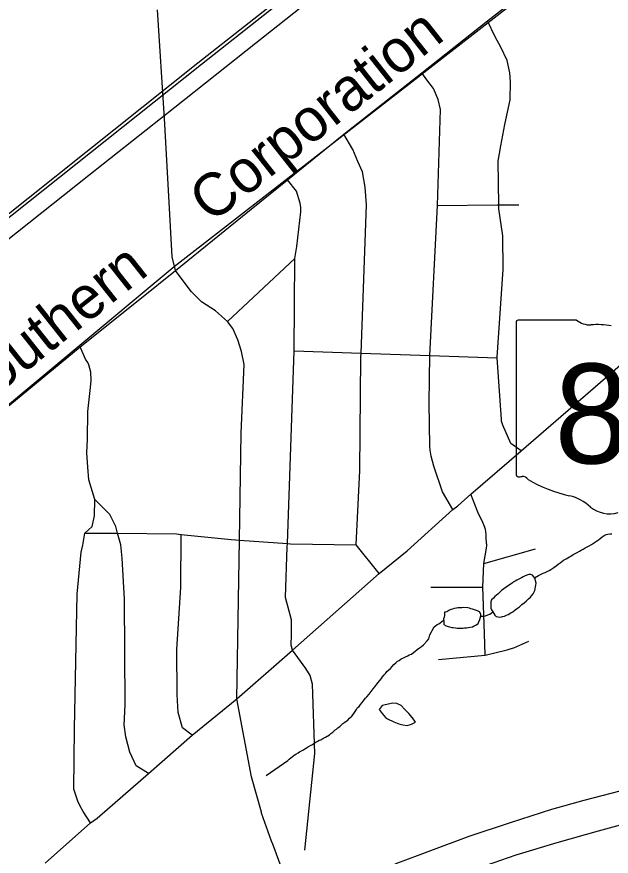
# Model space of a CAD drawing. Extents: x 0 to 34, y 0 to 22.
# Drawn here: x 7.421 to 8.206, y 14.779 to 15.889 of the extents above; entities that cross this region are included whole.
import ezdxf

# ---------------------------------------------------------------- set-up
doc = ezdxf.new("R2010")
doc.units = 0
for name, color, linetype in [('GM_X_City_Street', 7, 'Continuous'), ('GM_X_Interstate_Route', 7, 'Continuous'), ('GM_X_Minor_Lake', 7, 'Continuous'), ('GM_X_Minor_River', 7, 'Continuous'), ('GM_X_Rail_Line', 7, 'Continuous'), ('GM_X_Rail_Line_Text', 7, 'Continuous'), ('GM_X_State_Location', 7, 'Continuous'), ('GM_X_State_Route', 7, 'Continuous'), ('GM_X_State_Shield', 7, 'Continuous'), ('GM_X_US_Route', 7, 'Continuous')]:
    doc.layers.add(name, color=color, linetype=linetype)

msp = doc.modelspace()

# ---------------------------------------------------------------- linework, layer by layer
at = {"layer": 'GM_X_City_Street'}
for p, q in [((8.0578, 15.6405), (8.0841, 15.6407)), ((7.699, 15.4863), (7.7879, 15.5698)), ((8.0379, 15.1664), (8.1062, 15.1859)), ((7.9677, 15.1353), (8.0364, 15.1349))]:
    msp.add_line(p, q, dxfattribs=at)
for points in [[(8.0874, 15.3152), (8.0737, 15.3249), (8.0628, 15.3493), (8.062, 15.3519), (8.0613, 15.3547), (8.061, 15.3569), (8.0556, 15.4382), (8.0555, 15.4393), (8.0635, 15.555), (8.0631, 15.5995), (8.0579, 15.6352), (8.0578, 15.6405), (8.0566, 15.6985), (8.0602, 15.7187), (8.0655, 15.747), (8.0726, 15.7796), (8.0731, 15.8032), (8.0724, 15.815), (8.0685, 15.8312), (8.0604, 15.8489), (8.0528, 15.8628), (8.0427, 15.884)], [(7.997, 15.2378), (7.9834, 15.2612), (7.9718, 15.2951), (7.9682, 15.3085), (7.9669, 15.3164), (7.9665, 15.3216), (7.9657, 15.3787), (7.9665, 15.4413), (7.9766, 15.6397), (7.9808, 15.7668), (7.9776, 15.7798), (7.9715, 15.7944), (7.9624, 15.8057), (7.9559, 15.8151)], [(7.8996, 15.153), (7.8693, 15.1912), (7.8738, 15.2894), (7.8754, 15.4388), (7.8756, 15.4444), (7.8828, 15.6408), (7.881, 15.664), (7.8773, 15.6843), (7.8715, 15.6979), (7.8647, 15.7138), (7.8527, 15.7338)], [(7.8012, 14.7872), (7.8146, 14.915), (7.8115, 15.0068), (7.8085, 15.0185), (7.8028, 15.0276), (7.7849, 15.0518), (7.7831, 15.0586), (7.7838, 15.0725), (7.7838, 15.0918), (7.7756, 15.1214), (7.7781, 15.1885), (7.7782, 15.1929), (7.7874, 15.4474), (7.7879, 15.5698), (7.7909, 15.5857), (7.7962, 15.6315), (7.796, 15.6334), (7.796, 15.6369), (7.795, 15.6429), (7.7903, 15.6586), (7.7783, 15.6736)], [(7.9766, 15.6397), (8.0553, 15.6405), (8.0578, 15.6405)], [(7.5946, 14.8886), (7.5784, 14.8987), (7.57, 14.9169), (7.5649, 14.9374), (7.5625, 14.9529), (7.5638, 14.9791), (7.5629, 15.1193), (7.5599, 15.1736), (7.5579, 15.1911), (7.5538, 15.2063), (7.5514, 15.2155), (7.5436, 15.2312), (7.5236, 15.2512), (7.516, 15.2772), (7.5143, 15.2938), (7.5131, 15.3127), (7.514, 15.3306), (7.5145, 15.3674), (7.5181, 15.399), (7.5189, 15.4084), (7.5183, 15.4195), (7.516, 15.429), (7.5143, 15.432), (7.5112, 15.4365), (7.5045, 15.4529)], [(7.7874, 15.4474), (7.8756, 15.4444), (7.9665, 15.4413), (8.0556, 15.4382)], [(7.5178, 14.8233), (7.5083, 14.8385), (7.5043, 14.8457), (7.5014, 14.8521), (7.4962, 14.868), (7.4968, 14.9476), (7.5006, 15.1257), (7.5055, 15.1812), (7.5077, 15.1907), (7.5107, 15.2067), (7.5201, 15.2155), (7.5234, 15.2296), (7.5236, 15.2512)], [(8.0396, 15.0453), (8.0387, 15.0738), (8.0364, 15.1349), (8.0379, 15.1664), (8.0414, 15.1865), (8.0417, 15.1903), (8.0411, 15.1996), (8.0408, 15.2041), (8.0403, 15.2086), (8.04, 15.2113), (8.0387, 15.2154), (8.0367, 15.2206), (8.0298, 15.2342), (8.0208, 15.2579)], [(7.5107, 15.2067), (7.5538, 15.2063), (7.6315, 15.2055), (7.6378, 15.2049), (7.7041, 15.1983), (7.7099, 15.1978), (7.7148, 15.1974), (7.7782, 15.1929), (7.7825, 15.1926), (7.8693, 15.1912)], [(7.6523, 14.9395), (7.6397, 14.9492), (7.6338, 14.9693), (7.6325, 14.9933), (7.6321, 15.0529), (7.6373, 15.1346), (7.6378, 15.2049)], [(7.9781, 15.0394), (8.0396, 15.0453), (8.0686, 15.0521), (8.0728, 15.0534), (8.0773, 15.0549), (8.0972, 15.0639)]]:
    msp.add_lwpolyline(points, dxfattribs=at)
at = {"layer": 'GM_X_Interstate_Route'}
for points in [[(7.9205, 14.7695), (7.9678, 14.7868), (8.0184, 14.8059), (8.073, 14.8241), (8.1279, 14.8414), (8.1706, 14.8535), (8.2301, 14.869), (8.281, 14.8809), (8.383, 14.9014), (8.6062, 14.9451), (8.8651, 14.996), (8.9001, 15.0028)], [(7.873, 14.7025), (7.9366, 14.729), (8.0198, 14.7601), (8.0806, 14.781), (8.1348, 14.7973), (8.1895, 14.813), (8.2377, 14.8261), (8.2893, 14.8384), (8.3875, 14.8584), (8.6106, 14.9021), (8.8639, 14.9516), (8.9001, 14.9587)]]:
    msp.add_lwpolyline(points, dxfattribs=at)
at = {"layer": 'GM_X_Minor_Lake'}
for points in [[(8.0476, 15.1061), (8.0512, 15.1001), (8.0523, 15.0982), (8.0543, 15.0964), (8.0566, 15.0957), (8.0597, 15.0954), (8.0627, 15.0962), (8.065, 15.0966), (8.068, 15.0979), (8.0702, 15.0991), (8.0736, 15.101), (8.0762, 15.1026), (8.0792, 15.105), (8.0822, 15.1074), (8.0848, 15.1093), (8.0882, 15.1121), (8.0912, 15.1144), (8.0942, 15.1172), (8.0968, 15.1195), (8.0997, 15.1219), (8.1008, 15.1238), (8.1031, 15.1262), (8.1045, 15.1289), (8.1052, 15.1308), (8.1059, 15.1327), (8.1063, 15.1354), (8.1066, 15.1377), (8.1069, 15.1404), (8.1052, 15.1468), (8.104, 15.1487), (8.1024, 15.1509), (8.1001, 15.152), (8.0974, 15.1519), (8.0948, 15.1511), (8.0918, 15.1495), (8.0899, 15.1487), (8.0877, 15.1475), (8.085, 15.1463), (8.0831, 15.1451), (8.0813, 15.1443), (8.0794, 15.1431), (8.0768, 15.1415), (8.0757, 15.141)], [(8.0757, 15.141), (8.0674, 15.1352), (8.0644, 15.1328), (8.0614, 15.1308), (8.0592, 15.1285), (8.0566, 15.1265), (8.0547, 15.1246), (8.0525, 15.1226), (8.0506, 15.1206), (8.048, 15.1183), (8.0473, 15.1156), (8.047, 15.1126), (8.0471, 15.1107), (8.0472, 15.1068), (8.0476, 15.1061)], [(7.986, 15.1019), (7.986, 15.1), (7.9857, 15.0977), (7.9854, 15.0954), (7.9847, 15.0931), (7.9848, 15.0896), (7.9852, 15.0858), (7.9883, 15.084), (7.9906, 15.0829), (7.9926, 15.0826), (7.9956, 15.0819), (7.9975, 15.0816), (8.0002, 15.0813), (8.0025, 15.081), (8.0059, 15.081), (8.0086, 15.0807), (8.0105, 15.0808), (8.0124, 15.0812), (8.0151, 15.0813), (8.0173, 15.0817), (8.0227, 15.0826), (8.0249, 15.0838), (8.0275, 15.085), (8.0302, 15.087), (8.0312, 15.0893), (8.0327, 15.0924), (8.0337, 15.097), (8.0337, 15.0993), (8.0321, 15.1023), (8.0297, 15.1037), (8.027, 15.1048), (8.0228, 15.1062), (8.0209, 15.1066), (8.019, 15.1073), (8.0167, 15.1076), (8.0167, 15.1076)], [(8.0167, 15.1076), (8.011, 15.1082), (8.0087, 15.1078), (8.006, 15.1077), (8.0037, 15.1076), (8.0018, 15.1072), (7.9988, 15.1068), (7.9965, 15.1059), (7.9943, 15.1055), (7.9916, 15.1043), (7.989, 15.1027), (7.9864, 15.1019), (7.9864, 15.1019), (7.986, 15.1019)], [(7.9036, 14.9787), (7.8995, 14.9733), (7.9033, 14.968), (7.9079, 14.9628), (7.9106, 14.9611)], [(7.9475, 14.9567), (7.9436, 14.9624), (7.9386, 14.968), (7.9333, 14.9733), (7.9287, 14.9785), (7.9229, 14.9815), (7.9176, 14.9819), (7.9036, 14.9787)], [(7.9106, 14.9611), (7.919, 14.9572), (7.9255, 14.9546), (7.9308, 14.9531), (7.9365, 14.9524), (7.9422, 14.954), (7.9475, 14.9567)]]:
    msp.add_lwpolyline(points, dxfattribs=at)
at = {"layer": 'GM_X_Minor_River'}
for points in [[(8.1047, 15.1476), (8.1101, 15.1507), (8.1119, 15.1515), (8.1138, 15.1523), (8.1161, 15.1535), (8.1191, 15.1547), (8.1217, 15.156), (8.124, 15.1572), (8.1266, 15.1584), (8.1304, 15.1611), (8.1333, 15.1635), (8.136, 15.1655), (8.1386, 15.1674), (8.1408, 15.169), (8.1431, 15.1706), (8.1449, 15.1718), (8.1468, 15.1726), (8.1487, 15.1738), (8.151, 15.175), (8.1528, 15.1762), (8.1558, 15.1782), (8.1577, 15.179), (8.1611, 15.1809), (8.1645, 15.1829), (8.1663, 15.1841), (8.169, 15.1853), (8.172, 15.1869), (8.1746, 15.1885), (8.1772, 15.1897), (8.1802, 15.1917), (8.1829, 15.1933), (8.1866, 15.1961), (8.1892, 15.1977), (8.1915, 15.1996), (8.1941, 15.2016), (8.1971, 15.2036), (8.1997, 15.2048), (8.2016, 15.2052), (8.2043, 15.2057), (8.2069, 15.2057)], [(8.0337, 15.0969), (8.0372, 15.0967), (8.0402, 15.0971), (8.0432, 15.0984), (8.0458, 15.0996), (8.0477, 15.1008), (8.0498, 15.1024)], [(7.7501, 14.8862), (7.7788, 14.9058), (7.7807, 14.9078), (7.7829, 14.9094), (7.7848, 14.9113), (7.787, 14.9129), (7.7893, 14.9145), (7.7923, 14.9161), (7.7941, 14.9173), (7.796, 14.9184), (7.7986, 14.9197), (7.8013, 14.9212), (7.8035, 14.9228), (7.8061, 14.9244), (7.8088, 14.9256), (7.8107, 14.9268), (7.8133, 14.9284), (7.8159, 14.93), (7.8185, 14.9316), (7.8204, 14.9328), (7.8223, 14.9332), (7.8249, 14.9348), (7.8287, 14.9368), (7.8339, 14.94), (7.8358, 14.9415), (7.8384, 14.9435), (7.8414, 14.9463), (7.8433, 14.9474), (7.8451, 14.949), (7.8481, 14.9514), (7.8515, 14.9549), (7.8541, 14.9565), (7.8559, 14.958), (7.8582, 14.9592), (7.8604, 14.962), (7.8634, 14.9647), (7.8652, 14.9667), (7.8671, 14.9694), (7.8697, 14.9732), (7.8711, 14.9759), (7.873, 14.9775), (7.8748, 14.9798), (7.877, 14.9826), (7.8796, 14.9861), (7.8815, 14.9884), (7.8833, 14.9903), (7.8863, 14.9935), (7.8889, 14.997), (7.8918, 15.0005), (7.894, 15.0032), (7.8966, 15.0067), (7.8999, 15.0113), (7.9025, 15.0144), (7.904, 15.0164), (7.9062, 15.0191), (7.9077, 15.021), (7.9095, 15.0234), (7.9121, 15.0257), (7.9144, 15.0277), (7.9166, 15.0304), (7.9188, 15.0328), (7.9214, 15.0351), (7.9236, 15.0371), (7.9259, 15.0383), (7.9285, 15.0402), (7.9315, 15.0418), (7.9345, 15.0431), (7.9375, 15.0443), (7.9394, 15.0455), (7.9421, 15.0467), (7.9447, 15.0486), (7.9465, 15.0502), (7.9499, 15.0526), (7.9529, 15.0549), (7.9555, 15.0565), (7.9581, 15.0589), (7.9629, 15.064), (7.9652, 15.0667), (7.9665, 15.072), (7.9687, 15.0759), (7.9698, 15.0778), (7.9724, 15.0825), (7.9742, 15.084), (7.9761, 15.0856), (7.9784, 15.0868), (7.9802, 15.088), (7.9847, 15.0914)]]:
    msp.add_lwpolyline(points, dxfattribs=at)
at = {"layer": 'GM_X_Rail_Line'}
for points in [[(6.6237, 15.1553), (6.6743, 15.1672), (6.7378, 15.1849), (6.814, 15.2116), (6.891, 15.2462), (6.9588, 15.2844), (7.0054, 15.3121), (7.0582, 15.3501), (7.2871, 15.5311), (7.6599, 15.8282), (8.0769, 16.1566), (8.5157, 16.5045), (8.8904, 16.7977), (8.9001, 16.8054)], [(6.6242, 15.153), (6.6748, 15.1649), (6.7385, 15.1827), (6.8148, 15.2095), (6.8921, 15.2442), (6.96, 15.2825), (7.0098, 15.3111), (7.0632, 15.3489), (7.289, 15.5277), (7.6646, 15.8264), (8.083, 16.1569), (8.5171, 16.5027), (8.8918, 16.7959), (8.9001, 16.8025)], [(6.6266, 14.9819), (6.6396, 14.9896), (6.6528, 14.9982), (6.6734, 15.0126), (6.6898, 15.0251), (7.0335, 15.2973), (7.1242, 15.3694), (7.23, 15.4532), (7.3475, 15.5463), (7.4216, 15.6051), (7.5158, 15.6797), (7.6294, 15.7697), (7.7359, 15.8545), (8.0929, 16.1372), (8.3833, 16.3675), (8.7147, 16.6305), (8.9001, 16.7773)], [(8.9001, 16.2761), (8.2846, 16.0525), (8.2351, 16.0308), (7.6286, 15.5585), (7.3522, 15.3285), (6.9809, 15.0864), (6.9468, 15.0706), (6.8568, 15.011), (6.7801, 14.9477), (6.7423, 14.9258), (6.4831, 14.826), (6.4161, 14.8066), (6.3197, 14.7585), (6.2075, 14.6898), (6.1801, 14.6771), (6.15, 14.6743), (6.1143, 14.6764), (6.1057, 14.6241), (6.068, 14.5413), (6.0488, 14.5029)]]:
    msp.add_lwpolyline(points, dxfattribs=at)
at = {"layer": 'GM_X_State_Route'}
for points in [[(7.6215, 15.652), (7.6159, 15.7546), (7.6065, 15.8986)], [(7.7115, 14.9873), (7.7849, 15.0518), (7.8996, 15.153), (7.9364, 15.1832), (7.997, 15.2378), (8.0037, 15.2425), (8.0208, 15.2579), (8.0874, 15.3152), (8.2772, 15.4796), (8.4913, 15.667), (8.6494, 15.8039), (8.7321, 15.8767)], [(7.6304, 15.5536), (7.6258, 15.572), (7.6215, 15.652)], [(7.7115, 14.9873), (7.7148, 15.1974), (7.717, 15.3388), (7.721, 15.4296), (7.7177, 15.4468), (7.7129, 15.4623), (7.7061, 15.4769), (7.699, 15.4863), (7.6831, 15.5005), (7.6647, 15.5125), (7.6509, 15.5262), (7.6304, 15.5536)], [(7.4582, 14.7703), (7.4619, 14.7736), (7.5178, 14.8233), (7.5267, 14.8298), (7.5946, 14.8886), (7.6523, 14.9395), (7.7115, 14.9873)], [(7.744, 14.8375), (7.7308, 14.8842), (7.7115, 14.9873)], [(7.7574, 14.7993), (7.7442, 14.8365), (7.744, 14.8375)], [(7.7719, 14.7606), (7.7588, 14.7955), (7.7574, 14.7993)]]:
    msp.add_lwpolyline(points, dxfattribs=at)
at = {"layer": 'GM_X_State_Shield'}
for p, q in [((8.0806, 15.4847), (8.0806, 15.2846)), ((8.1604, 15.4882), (8.0832, 15.4882))]:
    msp.add_line(p, q, dxfattribs=at)
for centre, radius, start, end in [((8.0836, 15.4852), 0.00305, 98.1301, 188.1301), ((8.1788, 15.5114), 0.0296, 231.6195, 271.1119), ((8.1886, 15.3758), 0.1064, 80.4867, 94.9883), ((8.0837, 15.2842), 0.00308, 171.9584, 258.3066), ((8.0841, 15.3046), 0.0235, 267.339, 280.6039), ((8.0889, 15.2731), 0.00848, 29.7484, 93.2717), ((8.196, 15.4529), 0.2019, 240.4129, 257.1985), ((8.1358, 15.1947), 0.0632, 47.1842, 75.836), ((8.2041, 15.2721), 0.0401, 230.7004, 286.2918)]:
    msp.add_arc(centre, radius, start, end, dxfattribs=at)
at = {"layer": 'GM_X_US_Route'}
for p, q in [((7.6304, 15.5536), (7.7191, 15.6256)), ((7.5832, 15.5158), (7.6304, 15.5536))]:
    msp.add_line(p, q, dxfattribs=at)
for points in [[(7.7191, 15.6256), (7.7783, 15.6736), (7.8527, 15.7338), (7.9559, 15.8151), (8.0427, 15.884), (8.1736, 15.9862), (8.1837, 15.9943)], [(7.1055, 15.1667), (7.1145, 15.173), (7.1925, 15.2203), (7.2935, 15.285), (7.4113, 15.3762), (7.5045, 15.4529), (7.5832, 15.5158)]]:
    msp.add_lwpolyline(points, dxfattribs=at)

# ---------------------------------------------------------------- texts
at = {"layer": 'GM_X_Rail_Line_Text'}
for s, height, rotation, p in [('Corporation', 0.056629, 38.2943, (7.6776, 15.6151)), ('Southern', 0.05663, 38.3763, (7.356, 15.3591))]:
    msp.add_text(s, height=height, rotation=rotation, dxfattribs=at).set_placement(p)
at = {"layer": 'GM_X_State_Location'}
msp.add_text('84', height=0.000189, rotation=0, dxfattribs=at).set_placement((8.1618, 15.3576))
at = {"layer": 'GM_X_State_Shield'}
msp.add_text('84', height=0.13184, dxfattribs=at).set_placement((8.1312, 15.2987))

doc.saveas('drawing.dxf')
